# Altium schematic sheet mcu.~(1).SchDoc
size A3
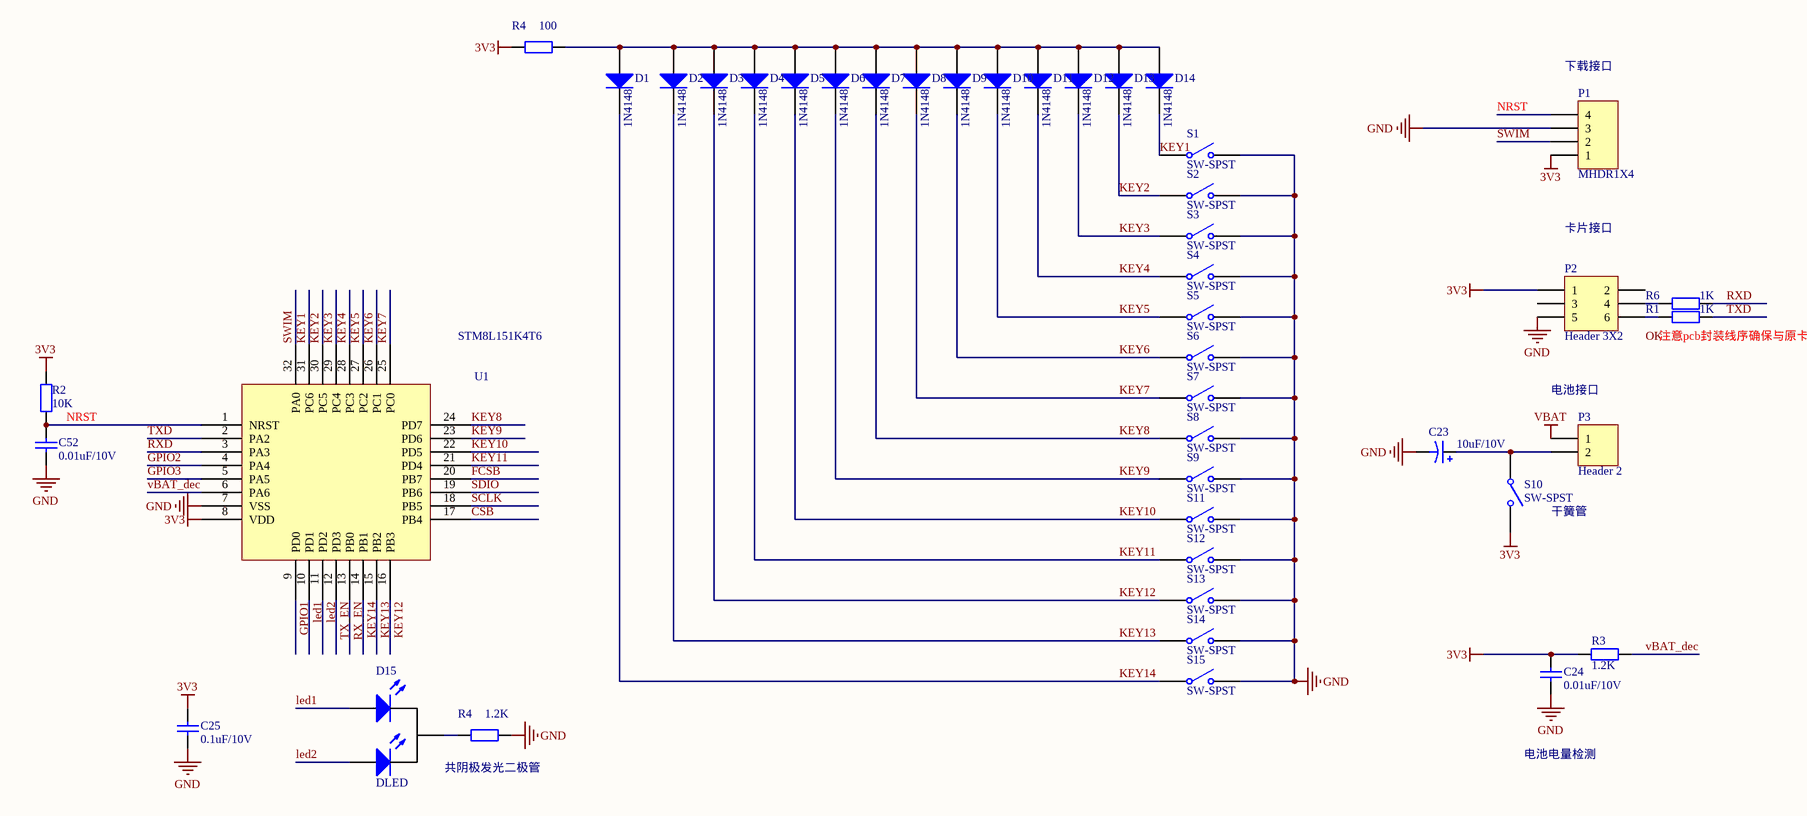
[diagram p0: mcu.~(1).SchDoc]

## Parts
(Parts that share a designator on the sheet are numbered #1, #2 ... from top to bottom, then left to right.)
C23  10uF/10V
C24  0.01uF/10V  [0603C]
C25  0.1uF/10V  [0603C]
C52  0.01uF/10V  [0603C]
D1  1N4148
D2  1N4148
D3  1N4148
D4  1N4148
D5  1N4148
D6  1N4148
D7  1N4148
D8  1N4148
D9  1N4148
D10  1N4148
D11  1N4148
D12  1N4148
D13  1N4148
D14  1N4148
D15  DLED
P1  MHDR1X4  [SIP4]
P2  Header 3X2
P3  Header 2
R1  1K  [0603R]
R2  10K  [0603R]
R3  1.2K  [0603R]
R4#1  100  [0603R]
R4#2  1.2K  [0603R]
R6  1K  [0603R]
S1  SW-SPST
S2  SW-SPST
S3  SW-SPST
S4  SW-SPST
S5  SW-SPST
S6  SW-SPST
S7  SW-SPST
S8  SW-SPST
S9  SW-SPST
S10  SW-SPST
S11  SW-SPST
S12  SW-SPST
S13  SW-SPST
S14  SW-SPST
S15  SW-SPST
U1  STM8L151K4T6  [QFP80P900X900X245-32N]

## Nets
3V3: C24.1 C25.1 P1.1 P2.1 R2.2 R3.2 R4#1.2 S10.2(NO) U1.8(VDD)
GND: C23.2 C24.2 C25.2 C52.2 P1.3 P2.5 R4#2.1 S1.2(NO) S2.2(NO) S3.2(NO) S4.2(NO) S5.2(NO) S6.2(NO) S7.2(NO) S8.2(NO) S9.2(NO) S11.2(NO) S12.2(NO) S13.2(NO) S14.2(NO) S15.2(NO) U1.7(VSS)
VBAT: P3.1
CSB: U1.17(PB4)
FCSB: U1.20(PB7)
GPIO1: U1.9(PD0)
GPIO2: U1.4(PA4)
GPIO3: U1.5(PA5)
KEY1: D14.2(K) S1.1(COMMON) U1.31(PC6)
KEY2: D13.2(K) S2.1(COMMON) U1.30(PC5)
KEY3: D12.2(K) S3.1(COMMON) U1.29(PC4)
KEY4: D11.2(K) S4.1(COMMON) U1.28(PC3)
KEY5: D10.2(K) S5.1(COMMON) U1.27(PC2)
KEY6: D9.2(K) S6.1(COMMON) U1.26(PC1)
KEY7: D8.2(K) S7.1(COMMON) U1.25(PC0)
KEY8: D7.2(K) S8.1(COMMON) U1.24(PD7)
KEY9: D6.2(K) S9.1(COMMON) U1.23(PD6)
KEY10: D5.2(K) S11.1(COMMON) U1.22(PD5)
KEY11: D4.2(K) S12.1(COMMON) U1.21(PD4)
KEY12: D3.2(K) S13.1(COMMON) U1.16(PB3)
KEY13: D2.2(K) S14.1(COMMON) U1.15(PB2)
KEY14: D1.2(K) S15.1(COMMON) U1.14(PB1)
led1: D15.1(A) U1.10(PD1)
led2: D15.3(A) U1.11(PD2)
NRST: C52.1 P1.4 R2.1 U1.1(NRST)
RX_EN: U1.13(PB0)
RXD: R6.1 U1.3(PA3)
SCLK: U1.18(PB5)
SDIO: U1.19(PB6)
SWIM: P1.2 U1.32(PA0)
TX_EN: U1.12(PD3)
TXD: R1.1 U1.2(PA2)
vBAT_dec: R3.1 U1.6(PA6)
NetC23_1: C23.1 P3.2 S10.1(COMMON)
NetD1_1: D1.1(A) D2.1(A) D3.1(A) D4.1(A) D5.1(A) D6.1(A) D7.1(A) D8.1(A) D9.1(A) D10.1(A) D11.1(A) D12.1(A) D13.1(A) D14.1(A) R4#1.1
NetD15_2: D15.2(K) R4#2.2
NetP2_4: P2.4 R6.2
NetP2_6: P2.6 R1.2

Not connected (* = marked no-connect by the designer): P2 2 3

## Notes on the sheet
- (near P1) 下载接口
- 卡片接口
- (near R1) 注意pcb封装线序确保与原卡片接口一致
- (near P3) 电池接口
- 干簧管
- 共阴极发光二极管
- 电池电量检测
- Labels drawn without touching a wire or pin: OK

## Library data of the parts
C23 = Cap Pol1: Polarized Capacitor (Radial); Value: 100pF
C24 C25 C52 = Cap: Capacitor; Value: 106
D1-D14 = Diode: Default Diode
P1 = MHDR1X4: Header, 4-Pin
P2 = Header 3X2: Header, 3-Pin, Dual row
P3 = Header 2: Header, 2-Pin
R1-R3 R4#1 R4#2 R6 = Res2: Resistor; Value: 10K/5%/1/8W
S1-S15 = SW-SPST: Single-Pole, Single-Throw Switch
